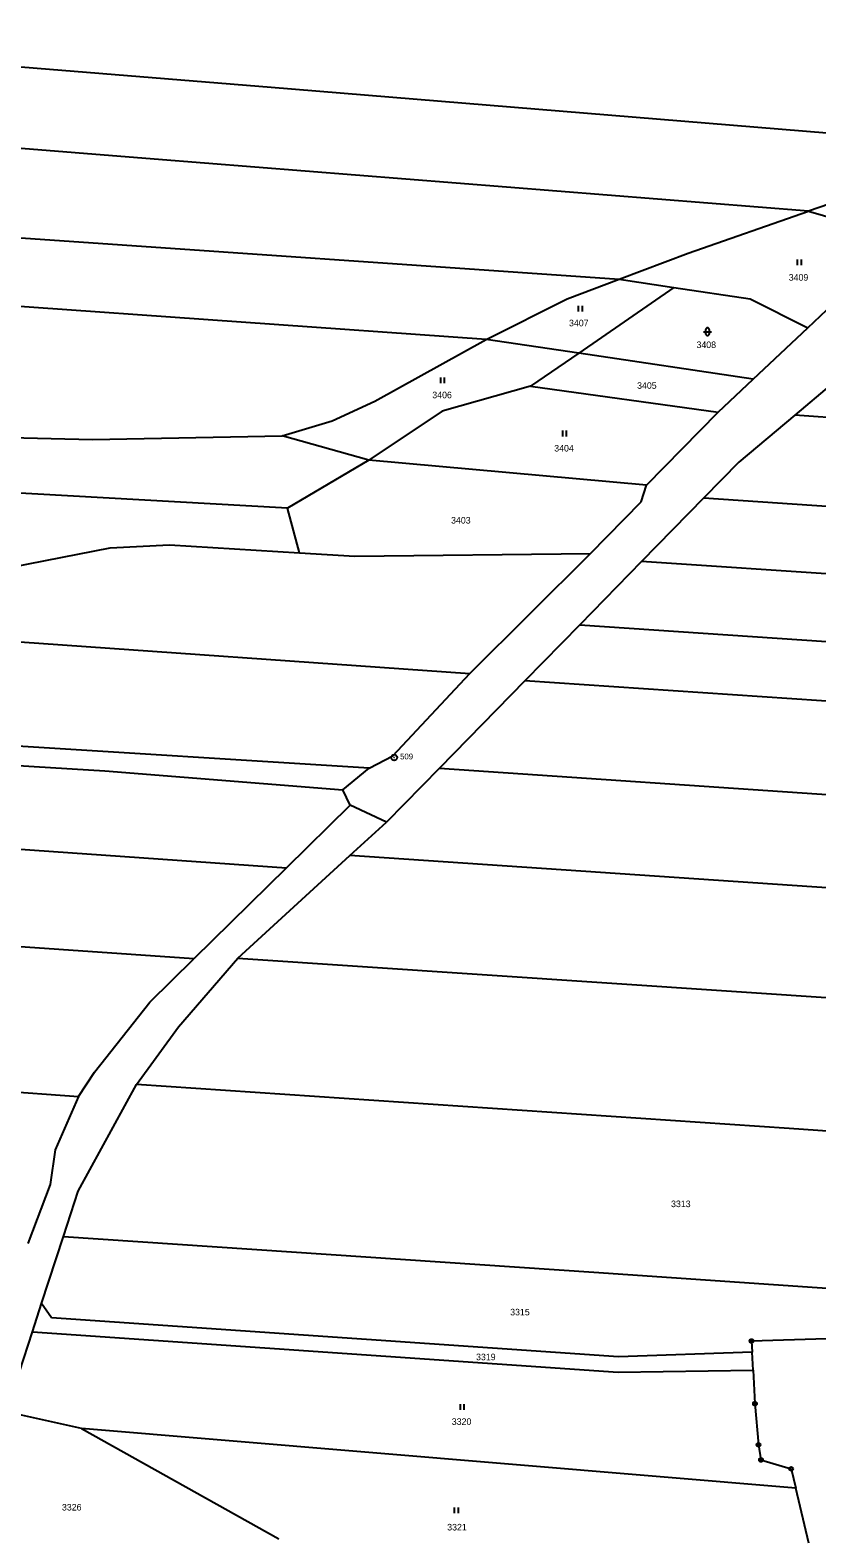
# Model space of a CAD drawing. Extents: x -618848 to -615803, y -1044450 to -1042254.
# Drawn here: x -617807.4 to -617604, y -1043703.1 to -1043313.1 of the extents above; entities that cross this region are included whole.
import ezdxf

# ---------------------------------------------------------------- set-up
doc = ezdxf.new("R2010")
doc.units = 0
doc.header["$LTSCALE"] = 0.68
for name, color, linetype, lineweight in [('1', 7, 'Continuous', 25), ('3', 7, 'Continuous', 25), ('8', 7, 'Continuous', 25)]:
    doc.layers.add(name, color=color, linetype=linetype, lineweight=lineweight)
doc.layers.add('2', color=7, linetype='Continuous')

msp = doc.modelspace()

# ---------------------------------------------------------------- linework, layer by layer
at = {"layer": '1'}
for p, q in [((-617925.72, -1043313.06), (-617745.12, -1043327.84)), ((-617745.12, -1043327.84), (-617564.53, -1043342.63)), ((-617775.33, -1043346.42), (-617944.47, -1043332.93)), ((-617606.19, -1043359.92), (-617775.33, -1043346.42)), ((-617572.36, -1043348.09), (-617606.19, -1043359.92)), ((-617637.26, -1043370.79), (-617606.19, -1043359.92)), ((-617606.19, -1043359.92), (-617575.37, -1043368.76)), ((-617809.82, -1043366.74), (-617655.1, -1043377.5)), ((-617655.1, -1043377.5), (-617637.26, -1043370.79)), ((-617689.51, -1043393.05), (-617874.13, -1043380.06)), ((-617668.58, -1043382.57), (-617655.1, -1043377.5)), ((-617640.99, -1043379.62), (-617665.58, -1043396.6)), ((-617655.1, -1043377.5), (-617640.99, -1043379.62)), ((-617640.99, -1043379.62), (-617621.29, -1043382.6)), ((-617689.51, -1043393.05), (-617668.58, -1043382.57)), ((-617621.29, -1043382.6), (-617606.34, -1043390.05)), ((-617606.34, -1043390.05), (-617601.44, -1043385.43)), ((-617620.48, -1043403.37), (-617606.34, -1043390.05)), ((-617718.27, -1043409), (-617689.51, -1043393.05)), ((-617665.58, -1043396.6), (-617689.51, -1043393.05)), ((-617665.58, -1043396.6), (-617678.01, -1043405.18)), ((-617620.48, -1043403.37), (-617665.58, -1043396.6)), ((-617629.51, -1043411.88), (-617620.48, -1043403.37)), ((-617678.01, -1043405.18), (-617700.89, -1043411.59)), ((-617678.01, -1043405.18), (-617629.51, -1043411.88)), ((-617600.29, -1043404.74), (-617609.74, -1043412.67)), ((-617729.35, -1043414.15), (-617718.27, -1043409)), ((-617742.28, -1043417.98), (-617729.35, -1043414.15)), ((-617700.89, -1043411.59), (-617719.81, -1043424.31)), ((-617648.04, -1043430.78), (-617629.51, -1043411.88)), ((-617609.74, -1043412.67), (-617624.15, -1043424.77)), ((-617505.98, -1043419.71), (-617609.74, -1043412.67)), ((-617832.85, -1043417.99), (-617791.3, -1043418.95)), ((-617791.3, -1043418.95), (-617742.28, -1043417.98)), ((-617719.81, -1043424.31), (-617742.28, -1043417.98)), ((-617719.81, -1043424.31), (-617740.84, -1043436.7)), ((-617648.04, -1043430.78), (-617719.81, -1043424.31)), ((-617624.15, -1043424.77), (-617633.21, -1043434.03)), ((-617740.84, -1043436.7), (-617877.79, -1043429.01)), ((-617649.45, -1043435.09), (-617648.04, -1043430.78)), ((-617633.21, -1043434.03), (-617649.31, -1043450.49)), ((-617633.21, -1043434.03), (-617478.58, -1043444.51)), ((-617737.77, -1043448.27), (-617740.84, -1043436.7)), ((-617662.56, -1043448.46), (-617649.45, -1043435.09)), ((-617786.69, -1043446.94), (-617771.37, -1043446.16)), ((-617771.37, -1043446.16), (-617737.77, -1043448.27)), ((-617817.58, -1043453.06), (-617786.69, -1043446.94)), ((-617737.77, -1043448.27), (-617723.43, -1043449.17)), ((-617723.43, -1043449.17), (-617662.56, -1043448.46)), ((-617693.76, -1043479.46), (-617662.56, -1043448.46)), ((-617649.31, -1043450.49), (-617665.33, -1043466.87)), ((-617457.63, -1043463.48), (-617649.31, -1043450.49)), ((-617852.02, -1043468.33), (-617693.76, -1043479.46)), ((-617665.33, -1043466.87), (-617679.49, -1043481.35)), ((-617665.33, -1043466.87), (-617551.06, -1043474.62)), ((-617713.67, -1043500.8), (-617693.76, -1043479.46)), ((-617679.49, -1043481.35), (-617701.61, -1043503.98)), ((-617548.92, -1043490.2), (-617679.49, -1043481.35)), ((-617719.72, -1043504), (-617866.91, -1043494.7)), ((-617867.25, -1043499.69), (-617788.09, -1043504.69)), ((-617719.72, -1043504), (-617713.67, -1043500.8)), ((-617788.09, -1043504.69), (-617726.6, -1043509.53)), ((-617726.6, -1043509.53), (-617719.72, -1043504)), ((-617701.61, -1043503.98), (-617715.28, -1043517.96)), ((-617701.61, -1043503.98), (-617545.76, -1043514.54)), ((-617724.63, -1043513.54), (-617726.6, -1043509.53)), ((-617741.12, -1043529.77), (-617724.63, -1043513.54)), ((-617715.28, -1043517.96), (-617724.63, -1043513.54)), ((-617900.51, -1043518.56), (-617741.12, -1043529.77)), ((-617724.73, -1043526.6), (-617715.28, -1043517.96)), ((-617753.71, -1043553.12), (-617724.73, -1043526.6)), ((-617552.06, -1043538.3), (-617724.73, -1043526.6)), ((-617741.12, -1043529.77), (-617765.04, -1043553.32)), ((-617765.04, -1043553.32), (-617923.38, -1043542.18)), ((-617776.41, -1043564.51), (-617765.04, -1043553.32)), ((-617769.05, -1043570.84), (-617753.71, -1043553.12)), ((-617753.71, -1043553.12), (-617570.88, -1043565.38)), ((-617790.75, -1043582.57), (-617776.41, -1043564.51)), ((-617779.92, -1043585.77), (-617769.05, -1043570.84)), ((-617941.26, -1043578.58), (-617794.92, -1043588.87)), ((-617794.92, -1043588.87), (-617790.75, -1043582.57)), ((-617794.94, -1043613.37), (-617779.92, -1043585.77)), ((-617611.2, -1043597.2), (-617779.92, -1043585.77)), ((-617794.92, -1043588.87), (-617800.91, -1043602.67)), ((-617442.49, -1043608.64), (-617611.2, -1043597.2)), ((-617800.91, -1043602.67), (-617802.18, -1043611.65)), ((-617802.18, -1043611.65), (-617807.96, -1043626.95)), ((-617798.77, -1043625.09), (-617794.94, -1043613.37)), ((-617804.43, -1043642.47), (-617798.77, -1043625.09)), ((-617798.77, -1043625.09), (-617661.65, -1043634.38)), ((-617661.65, -1043634.38), (-617524.53, -1043643.66)), ((-617806.81, -1043649.8), (-617804.43, -1043642.47)), ((-617801.87, -1043646.13), (-617804.43, -1043642.47)), ((-617655.32, -1043656.21), (-617801.87, -1043646.13)), ((-617813.54, -1043670.48), (-617806.81, -1043649.8)), ((-617806.81, -1043649.8), (-617655.39, -1043660.22)), ((-617601.5, -1043651.55), (-617620.9, -1043652.15)), ((-617620.9, -1043652.15), (-617620.74, -1043655.06)), ((-617620.74, -1043655.06), (-617655.32, -1043656.21)), ((-617620.49, -1043659.68), (-617620.74, -1043655.06)), ((-617655.39, -1043660.22), (-617620.49, -1043659.68)), ((-617620.49, -1043659.68), (-617620.02, -1043668.35)), ((-617620.02, -1043668.35), (-617619.1, -1043678.98)), ((-617794.1, -1043674.75), (-617813.54, -1043670.48)), ((-617609.48, -1043690.18), (-617794.1, -1043674.75)), ((-617794.1, -1043674.75), (-617743.08, -1043703.31)), ((-617619.1, -1043678.98), (-617618.46, -1043682.91)), ((-617618.46, -1043682.91), (-617610.67, -1043685.22)), ((-617610.67, -1043685.22), (-617609.48, -1043690.18)), ((-617606.05, -1043704.44), (-617609.48, -1043690.18))]:
    msp.add_line(p, q, dxfattribs=at)
at = {"layer": '3'}
for p, q in [((-617609.011, -1043373.89), (-617609.011, -1043372.39)), ((-617608.01, -1043373.89), (-617608.01, -1043372.39)), ((-617665.601, -1043385.84), (-617665.601, -1043384.34)), ((-617664.6, -1043385.84), (-617664.6, -1043384.34)), ((-617633.291, -1043391.061), (-617631.289, -1043391.061)), ((-617632.791, -1043390.561), (-617632.791, -1043391.562)), ((-617631.789, -1043391.562), (-617631.789, -1043390.561)), ((-617701.251, -1043404.39), (-617701.251, -1043402.89)), ((-617700.25, -1043404.39), (-617700.25, -1043402.89)), ((-617669.721, -1043418.13), (-617669.721, -1043416.63)), ((-617668.72, -1043418.13), (-617668.72, -1043416.63)), ((-617696.151, -1043669.96), (-617696.151, -1043668.46)), ((-617695.15, -1043669.96), (-617695.15, -1043668.46)), ((-617697.671, -1043696.71), (-617697.671, -1043695.21)), ((-617696.67, -1043696.71), (-617696.67, -1043695.21))]:
    msp.add_line(p, q, dxfattribs=at)
for centre, start, end in [((-617632.29, -1043390.5609), 0, 180), ((-617632.29, -1043391.5609), 180, 359.98789)]:
    msp.add_arc(centre, 0.5, start, end, dxfattribs=at)
at = {"layer": '8'}
for centre, radius in [((-617713.28, -1043501.2198), 0.75), ((-617713.28, -1043501.2198), 0.03), ((-617620.9, -1043652.1499), 0.5), ((-617620.9, -1043652.1499), 0.0303), ((-617620.02, -1043668.3499), 0.5), ((-617620.02, -1043668.3499), 0.0303), ((-617619.1, -1043678.9799), 0.5), ((-617619.1, -1043678.9799), 0.0303), ((-617618.46, -1043682.9099), 0.5), ((-617618.46, -1043682.9099), 0.0303), ((-617610.67, -1043685.2199), 0.5), ((-617610.67, -1043685.2199), 0.0303)]:
    msp.add_circle(centre, radius, dxfattribs=at)

# ---------------------------------------------------------------- texts
at = {"layer": '2'}
for s, p in [('3409', (-617611.29, -1043377.865)), ('3407', (-617668.09, -1043389.665)), ('3408', (-617635.13, -1043395.295)), ('3406', (-617703.43, -1043408.275)), ('3405', (-617650.49, -1043405.835)), ('3404', (-617671.91, -1043422.055)), ('3403', (-617698.58, -1043440.695)), ('3313', (-617641.71, -1043617.515)), ('3315', (-617683.3, -1043645.525)), ('3319', (-617692.12, -1043657.125)), ('3320', (-617698.39, -1043673.845)), ('3326', (-617799.17, -1043695.995)), ('3321', (-617699.58, -1043701.155))]:
    msp.add_text(s, height=1.7, dxfattribs=at).set_placement(p)
at = {"layer": '8'}
msp.add_text('509', height=1.5, dxfattribs=at).set_placement((-617711.75, -1043501.695))

doc.saveas('drawing.dxf')
